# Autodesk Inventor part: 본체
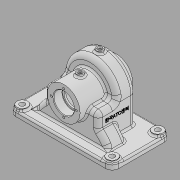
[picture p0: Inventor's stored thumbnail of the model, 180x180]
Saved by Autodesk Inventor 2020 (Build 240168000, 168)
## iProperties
Created: 2024-01
Part Number: 본체
Material: 일반
Document SubType Name: Modeling
Designer: 방송실
Density: 1 g/cm^3
Appearance: 기본값
Mass: 276.944 g
Surface Area: 911.068 cm^2
Volume: 276.944 cm^3
Author: 방송실
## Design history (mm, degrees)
sketch "스케치1"
  geometry: L1 (-88, 50)-(88, 50); L2 (88, 50)-(88, -50); L3 (88, -50)-(-88, -50); L4 (-88, -50)-(-88, 50); L5 (-88, 50)-(88, -50); L6 (88, 50)-(-88, -50); 1 further point
  constraints: 12 end point, 2 midpoint, 2 parallel, 1 horizontal, 1 perpendicular
  dimensions: "d0" = 176 distance of L1.start L1.end; "d1" = 100 distance of L1.end L2.end
extrude "돌출1" new body sketch "스케치1" distance "d2" = 9; taper "d3" = 0 deg
sketch "스케치2"
  geometry: L1 (0, 50)-(0, -50) reference; L2 (84, 45)-(56, 45); L3 (56, -45)-(84, -45); L4 (84, -45)-(84, 45); L5 (0, 50)-(9, 50) reference; 3 further points
  constraints: 6 end point, 2 horizontal, 1 horizontal alignment, 1 midpoint, 1 parallel, 1 vertical, 4 other
  dimensions: "d4" = 56 dimension on L1; "d5" = 5 distance between parallel lines of L5 L2; "d6" = 56 dimension on L4
revolve "회전1" sketch "스케치2" stored, may be unused: angle "d7" = 90 deg
node "작업 평면1"
sketch "스케치3"
  geometry: L1 (88, 9)-(-88, 9) reference; L2 (-46, 56)-(-46, 9); L3 (46, 56)-(46, 9); L4 (-46, 56)-(46, 56); C1 r 28 at (0, 56) reference; A1 r 46 centre (0, 56) between (-46, 56) and (46, 56); 1 further point
  constraints: 6 end point, 2 perpendicular, 2 point on circle, 2 point on line, 2 tangent, 1 centre point, 1 coincident, 1 vertical
  dimensions: "d9" = 92 diameter of A1
extrude "돌출2" join sketch "스케치3" distance "d10" = 32; taper "d11" = 0 deg
extrude "돌출3" join sketch "스케치3" distance "d12" = 64; taper "d13" = 0 deg
sketch "스케치4"
  geometry: L1 (88, 0)-(-88, 0) reference; C1 r 72 at (0, -24); 3 further points
  constraints: 1 centre point, 1 vertical alignment
  dimensions: "d14" = 72 radius of C1; "d15" = 48 distance edge to line of C1 L1
extrude "돌출4" join sketch "스케치4" distance "d16" = 32; taper "d17" = 0 deg
node "작업 평면2"
sketch "스케치5"
  geometry: L1 (46, 0)-(-46, 0) reference; C1 r 6 at (0, 17); C2 r 4 at (0, 17); 2 further points
  constraints: 2 centre point, 1 coincident, 1 midpoint, 1 vertical alignment
  dimensions: "d20" = 12 diameter of C1; "d21" = 8 diameter of C2; "d22" = 17 distance from line of C1.centre L1
extrude "돌출5" join sketch "스케치5" stored distance "d23" = 32; taper "d24" = 0 deg
extrude "돌출6" cut sketch "스케치5" distance "d25" = 2; taper "d26" = 0 deg
node "작업 평면3"
sketch "스케치6"
  geometry: L1 (46, 0)-(-46, 0) reference; C1 r 6 at (0, -17); C2 r 4 at (0, -17); 1 further point
  constraints: 2 centre point, 1 coincident, 1 vertical alignment
  dimensions: "d28" = 12 diameter of C1; "d29" = 8 diameter of C2; "d30" = 17 distance from line of C1.centre L1
extrude "돌출7" join sketch "스케치6" stored distance "d31" = 2; taper "d32" = 0 deg
extrude "돌출8" cut sketch "스케치6" distance "d33" = 2; taper "d34" = 0 deg
node "작업 평면4"
node "작업 평면6"
sketch "스케치8"
  geometry: L1 (-46, 56)-(-28, 56) reference; L2 (28, 56)-(46, 56) reference; L3 (-41, 51)-(-22.45, 51); L4 (22.45, 51)-(41, 51); L5 (-41, 51)-(-41, 28.991); L6 (41, 28.991)-(41, 51); L7 (88, 0)-(-88, 0) reference; L8 (-41, 28.991)-(41, 28.991); A1 r 72 centre (0, -24) between (-46, 31.39) and (-63.992, 9) reference; A2 r 72 centre (0, -24) between (63.992, 9) and (46, 31.39) reference; A3 r 67 centre (0, -24) between (-41, 28.991) and (-62.554, 0); A4 r 67 centre (0, -24) between (62.554, 0) and (41, 28.991); A5 r 28 centre (0, 56) between (28, 56) and (-28, 56) reference; A6 r 23 centre (0, 56) between (22.45, 51) and (-22.45, 51); 3 further points; 2 other entities
  constraints: 10 end point, 6 point on circle, 3 centre point, 2 point on line, 2 vertical, 2 other
  dimensions: "d40" = 5 radial gap between concentric circles of A1 A3; "d41" = 5 radial gap between concentric circles of A2 A4; "d43" = 5 radial gap between concentric circles of A5 A6; "d44" = 5 dimension on L5; "d45" = 5 dimension on L6; "d46" = 5 distance between parallel lines of L4 L2; "d47" = 5 distance between parallel lines of L3 L1
extrude "돌출10" cut sketch "스케치8" distance "d48" = 32; taper "d49" = 0 deg
node "작업 평면7"
sketch "스케치9"
  geometry: L1 (-41, 56)-(-41, -14); L2 (-41, -14)-(41, -14); L3 (41, -14)-(41, 56); A1 r 46 centre (0, 56) between (46, 56) and (-46, 56) reference; A2 r 41 centre (0, 56) between (41, 56) and (-41, 56); 1 further point
  constraints: 6 end point, 2 perpendicular, 2 point on circle, 2 tangent, 1 centre point, 1 vertical
  dimensions: "d51" = 5 radial gap between concentric circles of A1 A2; "d52" = 70 distance from line of A1.centre L2
extrude "돌출11" cut sketch "스케치9" distance "d53" = 22; taper "d54" = 0 deg
sketch "스케치10"
  geometry: L1 (28, 45)-(84, 45) reference; L2 (28, -45)-(84, -45) reference; L3 (56, 45)-(56, -45); L4 (73.5, 45)-(73.5, 30); L5 (73.5, 30)-(70.5, 30); L6 (70.5, 30)-(70.5, -30); L7 (70.5, -30)-(73.5, -30); L8 (73.5, -30)-(73.5, -45); 1 further point
  constraints: 12 end point, 4 perpendicular, 2 midpoint, 2 point on line, 1 vertical
  dimensions: "d55" = 29 diameter of L6 L3; "d56" = 35 diameter of L8 L3; "d57" = 15 distance of L7.end L8.end; "d58" = 35 diameter of L4 L3; "d59" = 15 distance of L4.start L4.end
node "작업 평면8"
sketch "스케치11"
  geometry: L1 (-41, 0)-(-41, 56) reference; L2 (41, 56)-(41, 0) reference; L3 (41, 28.991)-(-41, 28.991) reference; L4 (88, 0)-(-88, 0) reference; A1 r 72 centre (0, -24) between (-46, 31.39) and (-63.992, 9) reference; A2 r 72 centre (0, -24) between (63.992, 9) and (46, 31.39) reference; A3 r 67 centre (0, -24) between (-41, 28.991) and (-62.554, 0); A4 r 67 centre (0, -24) between (62.554, 0) and (41, 28.991); 1 further point
  constraints: 4 point on circle, 4 point on line, 2 centre point
  dimensions: "d61" = 5 radial gap between concentric circles of A1 A3; "d62" = 5 radial gap between concentric circles of A2 A4
extrude "돌출12" cut sketch "스케치11" distance "d63" = 22; taper "d64" = 0 deg
extrude "돌출13" cut sketch "스케치11" distance "d65" = 32; taper "d66" = 0 deg
revolve "회전2" stored, may be unused: angle "d67" = 90 deg
sketch "스케치12"
  geometry: C1 r 4 at (0, 0) reference; 2 further points
  constraints: 1 coincident
hole "구멍1" sketch "스케치12" at (0, 0) diameter "d68" = 5.1881; stored, may be unused: countersink angle "d72" = 90 deg, drill point angle "d74" = 0 deg; dims "d69" = 12, "d70" = 4, "d71" = 2, "d73" = 16
sketch "스케치13"
  geometry: C1 r 4 at (0, 0) reference; 2 further points
  constraints: 1 coincident
hole "구멍2" sketch "스케치13" at (0, 0) diameter "d75" = 5.1881; stored, may be unused: countersink angle "d79" = 90 deg, drill point angle "d81" = 0 deg; dims "d76" = 12, "d77" = 4, "d78" = 2, "d80" = 16
sketch "스케치14" dims "d82" = 43
  geometry: L1 (0, 0)-(0, 21.5); C1 r 28 at (0, 0) reference; 2 further points
  constraints: 2 coincident, 2 end point, 1 vertical, 1 vertical alignment, 2 other
hole "구멍3" sketch "스케치14" at (0, 21.5) diameter "d83" = 3.45873; stored, may be unused: countersink angle "d87" = 90 deg, drill point angle "d89" = 118 deg; dims "d84" = 8, "d85" = 4, "d86" = 2, "d88" = 10
sketch "스케치15" dims "d93" = 43
  geometry: L1 (0, 0)-(0, 21.5); C1 r 28 at (0, 0) reference; 2 further points
  constraints: 2 coincident, 2 end point, 1 vertical, 1 vertical alignment, 2 other
hole "구멍4" sketch "스케치15" at (0, 21.5) diameter "d94" = 3.45873; stored, may be unused: countersink angle "d98" = 90 deg, drill point angle "d100" = 118 deg; dims "d95" = 8, "d96" = 4, "d97" = 2, "d99" = 10
fillet "모깎기1" dims "d104" = 11
sketch "스케치16"
  geometry: L1 (77, -39)-(-77, -39); L2 (-77, -39)-(-77, 39); L3 (-77, 39)-(77, 39); L4 (77, 39)-(77, -39); L5 (77, -39)-(-77, 39); L6 (-77, -39)-(77, 39); C1 r 9 at (-77, 39); C2 r 9 at (77, 39); C3 r 9 at (77, -39); C4 r 9 at (-77, -39); 1 further point
  constraints: 12 end point, 4 centre point, 4 coincident, 2 midpoint, 2 parallel, 1 horizontal, 1 perpendicular
  dimensions: "d105" = 154 distance of L2.end L3.end; "d106" = 78 distance of L1.end L2.end; "d107" = 18 diameter of C1; "d108" = 18 diameter of C2; "d109" = 18 diameter of C3; "d110" = 18 diameter of C4
extrude "돌출14" join sketch "스케치16" distance "d111" = 4; taper "d112" = 0 deg
sketch "스케치17"
  geometry: C1 r 9 at (0, 0) reference; C2 r 9 at (0, -78) reference; C3 r 9 at (154, -78) reference; C4 r 9 at (154, 0) reference; 5 further points
  constraints: 4 coincident
hole "구멍5" sketch "스케치17" at (0, 0), (0, -78), (154, -78), (154, 0) diameter "d113" = 9; stored, may be unused: countersink angle "d117" = 90 deg, drill point angle "d119" = 118 deg; dims "d114" = 8, "d115" = 4, "d116" = 2, "d118" = 10
sketch "스케치18"
  geometry: L1 (-82, 0)-(-82, -9) reference; L2 (-71, -9)-(7, -9) reference; 2 further points
  constraints: 1 other
  dimensions: "d120" = 50 distance from line of point (-32, 31) L1; "d121" = 40 distance from line of point (-32, 31) L2
feature "엠보싱1" sketch "스케치18" dims "d122" = 0.5, "d123" = 0
fillet "모깎기3" dims "d125" = 3
fillet "모깎기4" dims "d126" = 0.6, "d127" = 3, "d128" = 5
fillet "모깎기5" dims "d129" = 3
chamfer "모따기1" distance "d130" = 1; stored, may be unused: second distance "d131" = 2, angle "d132" = 45 deg
fillet "모깎기7" dims "d134" = 8
fillet "모깎기8" dims "d135" = 3
fillet "모깎기9" dims "d136" = 3
fillet "모깎기10" dims "d137" = 8
fillet "모깎기11" dims "d138" = 8
fillet "모깎기12" dims "d139" = 8
fillet "모깎기13" dims "d140" = 3
fillet "모깎기14" dims "d141" = 3
fillet "모깎기15" dims "d142" = 3
fillet "모깎기16" dims "d143" = 3
node "솔리드1"
pattern_circular "원형 패턴1" dims angle "d91" = 360 deg
pattern_circular "원형 패턴2" dims angle "d102" = 360 deg
feature "A9D066F2-1C7D-4E18-AEED-F7BC21143FA4" dims "d113" = 9, "d114" = 8, "d115" = 4, "d116" = 2, "d117" = 90 deg, "d118" = 10, "d119" = 118 deg
other parameters: "d8" = -32, "d18" = 88, "d27" = 106, "d39" = -5, "d50" = -5, "d60" = -5
